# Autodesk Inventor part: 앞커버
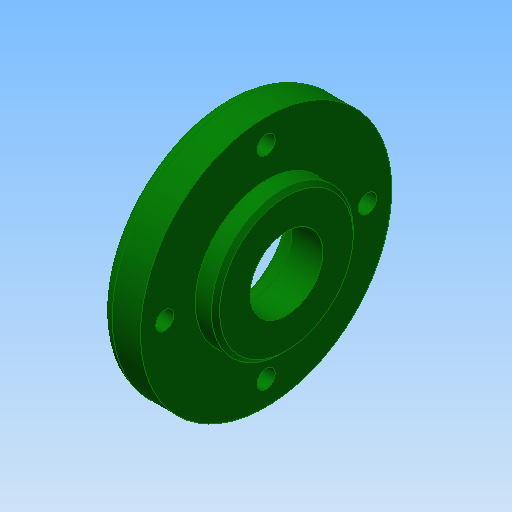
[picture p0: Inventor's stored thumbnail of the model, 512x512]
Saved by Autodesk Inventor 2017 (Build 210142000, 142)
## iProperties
Created: 2015-12
Part Number: 앞커버
Document SubType Name: Modeling
Designer: mdu
Density: 2.71 g/cm^3
Material: 알루미늄 6061
Appearance: 진녹색
Mass: 71.0233 g
Surface Area: 94.1949 cm^2
Volume: 26.2078 cm^3
Author: mdu
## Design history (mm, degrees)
sketch "스케치1"
  geometry: L1 (-7.5, 0)-(7.5, 0); L2 (-7.5, 0)-(-7.5, 31); L3 (-7.5, 31)-(2.5, 31); L4 (2.5, 31)-(2.5, 17.5); L5 (2.5, 17.5)-(7.5, 17.5); L6 (7.5, 17.5)-(7.5, 0); 2 further points
  constraints: 12 end point, 3 perpendicular, 1 coincident, 1 horizontal, 1 midpoint, 1 parallel
  dimensions: "d0" = 15 distance of L1.start L1.end; "d1" = 62 diameter of L3 L1; "d2" = 35 diameter of L5 L1; "d5" = 10 distance of L2.end L3.end
revolve "회전1" sketch "스케치1" stored, may be unused: angle "d6" = 90 deg
sketch "스케치2" dims "d42" = 50
  geometry: 3 further points
  constraints: 2 vertical alignment, 1 coincident, 2 other
hole "구멍1" sketch "스케치2" at (0, 25) diameter "d8" = 4.5; stored, may be unused: countersink angle "d12" = 90 deg, drill point angle "d14" = 118 deg; dims "d9" = 6, "d10" = 8, "d11" = 4.4, "d13" = 8
hole "구멍2" diameter "d20" = 18; stored, may be unused: countersink angle "d24" = 90 deg, drill point angle "d26" = 0 deg; dims "d18" = 10, "d19" = 10, "d21" = 6, "d22" = 8, "d23" = 4.4, "d25" = 8
hole "구멍3" diameter "d34" = 30; stored, may be unused: countersink angle "d38" = 90 deg, drill point angle "d40" = 0 deg; dims "d32" = 10, "d33" = 10, "d35" = 6, "d36" = 4, "d37" = 2, "d39" = 7.3
fillet "모깎기1" dims "d27" = 3, "d41" = 0.3
chamfer "모따기1" distance "d29" = 0.7; stored, may be unused: second distance "d30" = 2, angle "d31" = 30 deg
chamfer "모따기2" distance "d44" = 1; stored, may be unused: second distance "d45" = 2, angle "d46" = 45 deg
node "솔리드1"
pattern_circular "원형 패턴1" dims angle "d16" = 360 deg
